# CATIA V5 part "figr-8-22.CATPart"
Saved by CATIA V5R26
Part number: Part1
Bounding box of the stored display mesh (mm): x -60 to 60, y -75 to 75, z 0 to 10
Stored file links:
  D:\_Deepak\CATIA\CATIA V5-6R2016_Deepak\Resources\Part files\Partfiles\c08_catia_v5_6r2016_prt\figr-8-22.CATPart
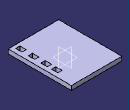
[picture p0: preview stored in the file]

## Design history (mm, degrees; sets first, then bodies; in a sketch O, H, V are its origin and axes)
Body1 (main body)
  Sketch1 on xy-plane, origin (0, 0, 0), H (1, 0, 0), V (0, 1, 0)
    line L1 (60, 75) -> (60, -75)
    line L2 (60, -75) -> (-60, -75)
    line L3 (-60, -75) -> (-60, 75)
    line L4 (-60, 75) -> (60, 75)
    length L2 = 120
    length L1 = 150
    vertical: L1 V, L3 V
    horizontal: L2 H, L4 H
    equidistance: L1 L3 O, L2 L4 O
  Pad1: profile Sketch1, direction (0, 0, 1), length 10
  Sketch2 on end face of Pad1, origin (0, 0, 10), H (1, 0, 0), V (0, 1, 0)
    point P1 (45, -59.5)
    line L1 (50, -52) -> (50, -67)
    line L2 (50, -67) -> (40, -67)
    line L3 (40, -67) -> (40, -52)
    line L4 (40, -52) -> (50, -52)
    reference projected line E1 (-60, -75) -> (60, -75) from edge [face of Pad1 from Sketch1.L2 | end face of Pad1]
    reference projected line E2 (60, -75) -> (60, 75) from edge [face of Pad1 from Sketch1.L1 | end face of Pad1]
    distance L2 E1 = 8
    distance L1 E2 = 10
    length L4 = 10
    length L3 = 15
    vertical: L1 V, L3 V
    horizontal: L2 H, L4 H
    equidistance: L1 L3 P1, L2 L4 P1
  Pocket1: profile Sketch2, direction (0, 0, -1), length 10
  RectPattern1: of Pocket1, direction 1 instances 4, spacing 20, along edge [face of Pad1 from Sketch1.L1 | end face of Pad1]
